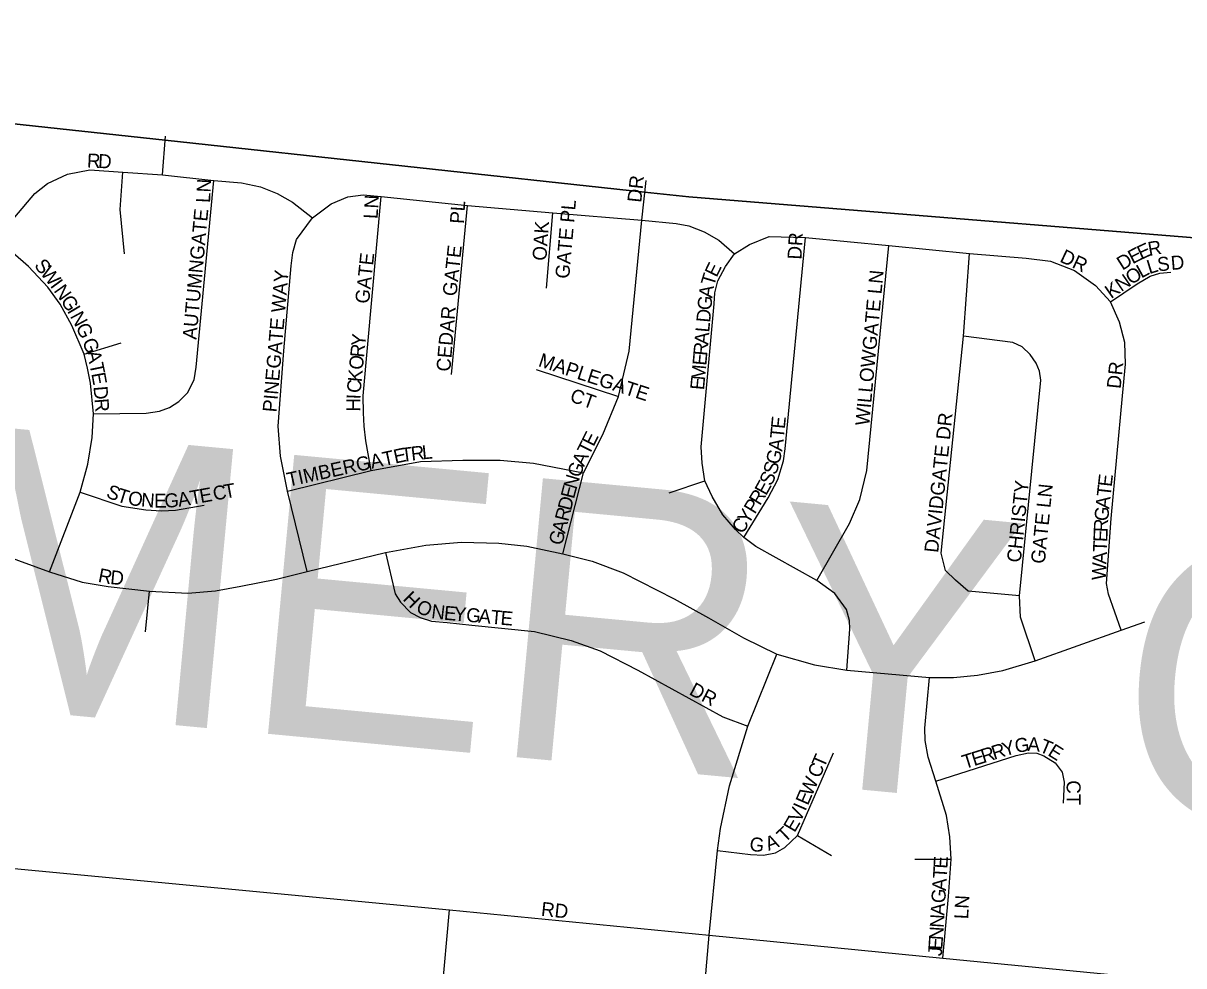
# Model space of a CAD drawing. Extents: x 0 to 680, y 0 to 440.
# Drawn here: x 73.29 to 85.58, y 268.17 to 278.15 of the extents above; entities that cross this region are included whole.
import ezdxf

# ---------------------------------------------------------------- set-up
doc = ezdxf.new("R2010")
doc.units = 0
for name, color, linetype in [('GM_X_Adjacent_County', 7, 'Continuous'), ('GM_X_Adjacent_County_Text', 7, 'Continuous'), ('GM_X_City_Street', 7, 'Continuous'), ('GM_X_City_Street_Text', 7, 'Continuous'), ('GM_X_County', 7, 'Continuous')]:
    doc.layers.add(name, color=color, linetype=linetype)

msp = doc.modelspace()

# ---------------------------------------------------------------- linework, layer by layer
at = {"layer": 'GM_X_Adjacent_County'}
for points in [[(47.02, 308.647), (47.02, 297.605), (47.136, 296.47), (47.708, 293.469), (47.673, 290.467), (48.191, 288.97), (48.899, 287.478), (50.382, 285.963), (52.043, 282.914), (53.205, 281.417), (53.473, 278.963), (55.844, 278.74), (63.104, 278.067), (70.999, 277.32), (74.792, 276.91), (79.867, 276.361), (80.338, 276.31), (87.389, 275.738), (92.667, 275.254), (94.764, 275.075), (102.624, 274.346)], [(47.02, 308.647), (47.02, 297.605), (47.136, 296.47), (47.708, 293.469), (47.673, 290.467), (48.191, 288.97), (48.899, 287.478), (50.382, 285.963), (52.043, 282.914), (53.205, 281.417), (53.473, 278.963), (55.844, 278.74), (63.104, 278.067), (70.999, 277.32), (74.792, 276.91), (79.867, 276.361), (80.338, 276.31), (87.389, 275.738), (92.667, 275.254), (94.764, 275.075), (102.624, 274.346)], [(102.624, 274.346), (94.764, 275.075), (92.667, 275.254), (87.389, 275.738), (80.338, 276.31), (79.867, 276.361), (74.792, 276.91), (70.999, 277.32), (63.104, 278.067), (55.844, 278.74), (53.473, 278.963), (53.205, 281.417), (52.043, 282.914), (50.382, 285.963), (48.899, 287.478), (48.191, 288.97), (47.673, 290.467), (47.708, 293.469), (47.136, 296.47), (47.02, 297.605), (47.02, 177.346)]]:
    msp.add_lwpolyline(points, dxfattribs=at)
at = {"layer": 'GM_X_City_Street'}
for points in [[(74.765, 276.544), (74.796, 276.954)], [(70.942, 275.595), (71.129, 275.57), (71.625, 275.511), (71.91, 275.482), (72.13, 275.465), (72.374, 275.465), (72.629, 275.523), (72.833, 275.65), (73.039, 275.839), (73.202, 276.096), (73.411, 276.346), (73.546, 276.451), (73.759, 276.551), (73.994, 276.598), (74.345, 276.573), (74.765, 276.544), (75.307, 276.485), (75.602, 276.457), (75.803, 276.417), (75.979, 276.347), (76.14, 276.253), (76.351, 276.087)], [(74.033, 274.016), (74.591, 274.022), (74.732, 274.041), (74.838, 274.081), (74.938, 274.146), (75.029, 274.236), (75.098, 274.373), (75.121, 274.509), (75.177, 275.104), (75.307, 276.485)], [(74.363, 275.706), (74.317, 276.175), (74.345, 276.573)], [(79.004, 272.534), (79.22, 273.39), (79.425, 273.797), (79.591, 274.197), (79.703, 274.677), (79.839, 276.063), (79.883, 276.484)], [(76.295, 272.347), (76.086, 273.197), (76.015, 273.565), (75.988, 273.884), (76.047, 274.682), (76.126, 275.58), (76.143, 275.722), (76.182, 275.859), (76.351, 276.087), (76.55, 276.237), (76.725, 276.31), (76.887, 276.332), (77.079, 276.314), (77.994, 276.22), (78.895, 276.14), (79.839, 276.063), (80.201, 276.028), (80.337, 276.004), (80.5, 275.94), (80.655, 275.852), (80.82, 275.706)], [(76.973, 273.414), (76.917, 273.729), (76.898, 273.884), (76.892, 274.026), (76.887, 274.204), (77.079, 276.314)], [(77.823, 274.431), (77.994, 276.22)], [(78.828, 275.343), (78.895, 276.14)], [(82.009, 271.302), (82.041, 271.736), (82.036, 271.829), (82.005, 271.944), (81.881, 272.113), (81.691, 272.25), (81.044, 272.611), (80.918, 272.706), (80.832, 272.789), (80.697, 272.947), (80.582, 273.141), (80.506, 273.305), (80.476, 273.492), (80.467, 273.666), (80.603, 275.178), (80.612, 275.295), (80.645, 275.422), (80.724, 275.573), (80.82, 275.706), (80.977, 275.805), (81.185, 275.89), (81.57, 275.881), (82.455, 275.794), (83.309, 275.712), (83.909, 275.663), (84.164, 275.629), (84.419, 275.53), (84.643, 275.372), (84.801, 275.201)], [(80.918, 272.706), (81.177, 273.124), (81.277, 273.32), (81.34, 273.518), (81.355, 273.644), (81.57, 275.881)], [(73.567, 272.341), (73.894, 273.186), (73.972, 273.481), (74.021, 273.763), (74.033, 274.016), (74.001, 274.339), (73.969, 274.496), (73.935, 274.646), (73.805, 274.948), (73.682, 275.174), (73.55, 275.353), (73.346, 275.573), (73.039, 275.839)], [(81.691, 272.25), (82.038, 272.853), (82.147, 273.108), (82.221, 273.414), (82.455, 275.794)], [(83.836, 272.09), (83.293, 272.138), (83.16, 272.253), (83.054, 272.358), (83.007, 272.539), (83.244, 274.838), (83.309, 275.712)], [(84.801, 275.201), (85.084, 275.391), (85.222, 275.47), (85.322, 275.504), (85.439, 275.512)], [(84.914, 271.727), (84.78, 272.106), (84.758, 272.22), (84.806, 272.907), (84.926, 274.206), (84.958, 274.54), (84.953, 274.771), (84.897, 274.983), (84.801, 275.201)], [(73.935, 274.646), (74.325, 274.766)], [(84.002, 271.402), (83.847, 271.862), (83.836, 272.09), (84.064, 274.372), (84.049, 274.465), (84.014, 274.551), (83.95, 274.644), (83.866, 274.722), (83.765, 274.771), (83.244, 274.838)], [(78.719, 274.485), (79.591, 274.197)], [(76.086, 273.197), (76.973, 273.414), (77.496, 273.509), (77.942, 273.523), (78.338, 273.523), (78.693, 273.491), (79.22, 273.39)], [(80.129, 273.179), (80.506, 273.305)], [(73.894, 273.186), (74.335, 273.037), (74.587, 272.997), (74.752, 272.988), (74.901, 272.995), (75.206, 273.048)], [(72.764, 272.634), (73.567, 272.341), (73.915, 272.232), (74.19, 272.189), (74.625, 272.137), (75.031, 272.118), (75.325, 272.141), (75.593, 272.19), (75.972, 272.264), (76.295, 272.347), (77.126, 272.547), (77.553, 272.626), (77.93, 272.655), (78.325, 272.645), (78.622, 272.615), (79.004, 272.534)], [(77.126, 272.547), (77.227, 272.111), (77.283, 272.021), (77.39, 271.912), (77.491, 271.858), (77.612, 271.822), (77.778, 271.806), (78.038, 271.777), (78.702, 271.711), (79.09, 271.617), (79.396, 271.508), (79.798, 271.302), (80.697, 270.81), (80.961, 270.708)], [(79.004, 272.534), (79.313, 272.457), (79.641, 272.333), (80.181, 272.058), (80.543, 271.856), (80.914, 271.645), (81.268, 271.471), (81.665, 271.36), (82.009, 271.302), (82.883, 271.224), (83.14, 271.225), (83.394, 271.248), (83.66, 271.298), (84.002, 271.402), (84.914, 271.727), (85.164, 271.814)], [(74.585, 271.708), (74.625, 272.137)], [(80.473, 267.6), (80.552, 268.499), (80.641, 269.394), (80.67, 269.626), (80.766, 270.078), (80.961, 270.708), (81.268, 271.471)], [(83.026, 268.256), (83.085, 268.907), (83.113, 269.304), (83.1, 269.54), (83.063, 269.763), (82.951, 270.127), (82.871, 270.38), (82.839, 270.557), (82.836, 270.689), (82.883, 271.224)], [(80.641, 269.394), (80.99, 269.353), (81.125, 269.346), (81.253, 269.371), (81.352, 269.427), (81.486, 269.554), (81.869, 270.426)], [(82.951, 270.127), (83.803, 270.399), (83.932, 270.426), (84.02, 270.424), (84.095, 270.396), (84.214, 270.323), (84.287, 270.223), (84.31, 270.116), (84.299, 269.895)], [(70.367, 269.473), (77.802, 268.765), (80.552, 268.499), (83.026, 268.256), (86.292, 267.936), (89.501, 267.603), (91.209, 267.449), (91.849, 267.397), (92.491, 267.422), (93.212, 267.516), (93.58, 267.534), (93.89, 267.521), (96.364, 267.28), (101.905, 266.772)], [(81.486, 269.554), (81.845, 269.342)], [(82.729, 269.304), (83.113, 269.304)], [(75.007, 265.475), (75.441, 265.433), (75.655, 265.41), (75.889, 265.413), (76.086, 265.452), (76.339, 265.55), (76.556, 265.69), (77.106, 266.138), (77.461, 266.474), (77.54, 266.646), (77.613, 266.834), (77.646, 267.011), (77.721, 267.865), (77.802, 268.765)]]:
    msp.add_lwpolyline(points, dxfattribs=at)
at = {"layer": 'GM_X_County'}
msp.add_lwpolyline([(102.624, 274.346), (94.764, 275.075), (92.667, 275.254), (87.389, 275.738), (80.338, 276.31), (79.867, 276.361), (74.792, 276.91), (70.999, 277.32), (63.104, 278.067), (55.844, 278.74), (53.473, 278.963), (53.205, 281.417), (52.043, 282.914), (50.382, 285.963), (48.899, 287.478), (48.191, 288.97), (47.673, 290.467), (47.708, 293.469), (47.136, 296.47), (47.02, 297.605), (47.02, 177.346)], dxfattribs=at)

# ---------------------------------------------------------------- texts
at = {"layer": 'GM_X_Adjacent_County_Text'}
msp.add_text('MONTGOMERY COUNTY', height=2.96462, rotation=354.6312, dxfattribs=at).set_placement((54.51, 272.637))
at = {"layer": 'GM_X_City_Street_Text'}
for s, height, rotation, p in [('R', 0.148, 357.4007, (73.962, 276.622)), ('D', 0.148, 356.6759, (74.079, 276.617)), ('LN', 0.1482, 86.989, (75.267, 276.244)), ('DR', 0.1482, 83.9946, (79.832, 276.245)), ('LN', 0.1482, 86.8222, (77.041, 276.074)), ('PL', 0.1482, 86.1879, (77.954, 276.022)), ('GATE PL', 0.1482, 84.9861, (79.069, 275.44)), ('AUTUMNGATE', 0.1482, 84.7521, (75.123, 274.796)), ('OAK', 0.1482, 86.1811, (78.828, 275.631)), ('DR', 0.1482, 86.8222, (81.528, 275.644)), ('R', 0.148, 10.0572, (85.21, 275.684)), ('GATE', 0.1482, 83.9264, (77.876, 275.254)), ('DR', 0.1482, 334.7921, (84.254, 275.628)), ('E', 0.148, 27.457, (85.034, 275.596)), ('E', 0.148, 24.8419, (85.125, 275.643)), ('S', 0.148, 309.0395, (73.399, 275.581)), ('GATE', 0.1482, 83.931, (76.95, 275.175)), ('E', 0.148, 64.1314, (80.63, 275.451)), ('D', 0.148, 32.4108, (84.927, 275.528)), ('L', 0.148, 17.0786, (85.211, 275.492)), ('S', 0.148, 6.0505, (85.303, 275.521)), ('D', 0.148, 4.9234, (85.445, 275.536)), ('W', 0.148, 308.6152, (73.464, 275.501)), ('PINEGATE WAY', 0.14823, 85.1021, (75.971, 274.027)), ('T', 0.148, 73.0861, (80.602, 275.357)), ('WILLOWGATE LN', 0.14823, 84.6282, (82.245, 273.884)), ('N', 0.148, 34.6357, (84.914, 275.301)), ('O', 0.148, 33.187, (85.02, 275.375)), ('L', 0.148, 28.8874, (85.127, 275.445)), ('I', 0.148, 306.188, (73.569, 275.369)), ('N', 0.148, 305.1693, (73.607, 275.317)), ('A', 0.148, 82.0862, (80.585, 275.234)), ('K', 0.148, 34.8237, (84.807, 275.227)), ('G', 0.148, 302.0957, (73.681, 275.212)), ('G', 0.148, 84.8679, (80.573, 275.106)), ('I', 0.148, 300.6939, (73.75, 275.103)), ('CEDAR', 0.1482, 85.1336, (77.81, 274.457)), ('D', 0.148, 84.857, (80.562, 274.976)), ('N', 0.148, 298.286, (73.782, 275.048)), ('G', 0.148, 294.0135, (73.843, 274.936)), ('Y', 0.148, 84.396, (76.908, 274.723)), ('A', 0.148, 84.857, (80.541, 274.742)), ('L', 0.148, 84.8604, (80.552, 274.872)), ('G', 0.148, 291.8582, (73.911, 274.782)), ('R', 0.148, 84.4104, (76.897, 274.606)), ('R', 0.148, 84.8693, (80.53, 274.625)), ('A', 0.148, 284.084, (73.958, 274.666)), ('O', 0.148, 84.396, (76.884, 274.476)), ('MAPLEGATE', 0.1482, 341.9956, (78.734, 274.521)), ('E', 0.148, 84.8604, (80.521, 274.521)), ('T', 0.148, 281.6636, (73.989, 274.541)), ('M', 0.148, 84.8553, (80.507, 274.365)), ('DR', 0.1482, 83.9946, (84.907, 274.275)), ('E', 0.148, 280.3024, (74.01, 274.44)), ('C', 0.148, 85.0891, (76.862, 274.23)), ('K', 0.148, 84.4177, (76.872, 274.346)), ('E', 0.148, 84.8575, (80.497, 274.262)), ('D', 0.148, 274.9234, (74.033, 274.302)), ('CT', 0.1482, 340.5566, (79.067, 274.149)), ('R', 0.148, 274.449, (74.044, 274.172)), ('H', 0.148, 89.6721, (76.858, 274.037)), ('I', 0.148, 87.463, (76.859, 274.166)), ('DAVIDGATE DR', 0.14823, 84.0745, (82.976, 272.54)), ('T', 0.148, 84.3007, (81.342, 273.747)), ('E', 0.148, 84.4529, (81.352, 273.851)), ('E', 0.148, 63.4349, (79.327, 273.661)), ('TIMBERGATE', 0.1482, 12.1816, (76.097, 273.243)), ('T', 0.148, 7.5351, (77.3, 273.504)), ('R', 0.148, 6.89, (77.403, 273.518)), ('L', 0.148, 5.5284, (77.518, 273.532)), ('T', 0.148, 63.4349, (79.28, 273.567)), ('A', 0.148, 82.621, (81.324, 273.613)), ('A', 0.148, 65.4509, (79.227, 273.45)), ('S', 0.148, 74.2915, (81.262, 273.362)), ('G', 0.148, 77.2379, (81.293, 273.471)), ('G', 0.148, 69.4828, (79.182, 273.33)), ('S', 0.148, 64.8058, (81.209, 273.243)), ('T', 0.148, 10.19, (75.427, 273.117)), ('N', 0.148, 73.5148, (79.146, 273.208)), ('E', 0.148, 61.2934, (81.154, 273.142)), ('CHRISTY', 0.1482, 84.193, (83.85, 272.436)), ('GATE LN', 0.1482, 84.193, (84.104, 272.423)), ('T', 0.148, 83.6477, (84.801, 273.134)), ('E', 0.148, 83.6625, (84.813, 273.238)), ('S', 0.148, 337.1637, (74.158, 273.137)), ('T', 0.148, 342.7548, (74.269, 273.091)), ('O', 0.148, 350.888, (74.391, 273.055)), ('N', 0.148, 355.4881, (74.533, 273.033)), ('E', 0.148, 0.1204, (74.676, 273.022)), ('G', 0.148, 2.484, (74.787, 273.022)), ('A', 0.148, 9.5001, (74.937, 273.03)), ('T', 0.148, 10.1963, (75.067, 273.052)), ('E', 0.148, 10.21, (75.17, 273.07)), ('C', 0.148, 10.2049, (75.311, 273.096)), ('D', 0.148, 75.5308, (79.088, 272.982)), ('E', 0.148, 75.5308, (79.12, 273.108)), ('R', 0.148, 58.684, (81.089, 273.036)), ('R', 0.148, 75.5308, (79.058, 272.868)), ('Y', 0.148, 58.6202, (80.967, 272.835)), ('P', 0.148, 58.6287, (81.035, 272.946)), ('G', 0.148, 84.9006, (84.776, 272.875)), ('A', 0.148, 83.6936, (84.787, 273.004)), ('C', 0.148, 58.628, (80.906, 272.735)), ('R', 0.148, 87.4007, (84.77, 272.76)), ('G', 0.148, 75.5308, (78.993, 272.615)), ('A', 0.148, 75.5308, (79.026, 272.742)), ('E', 0.148, 87.6927, (84.766, 272.656)), ('T', 0.148, 87.6766, (84.762, 272.551)), ('A', 0.148, 87.6823, (84.757, 272.421)), ('W', 0.148, 87.6791, (84.75, 272.252)), ('R', 0.148, 348.9044, (74.075, 272.238)), ('D', 0.148, 354.3582, (74.206, 272.214)), ('H', 0.148, 314.8764, (77.3, 272.048)), ('O', 0.148, 334.6292, (77.437, 271.924)), ('N', 0.148, 353.1184, (77.605, 271.854)), ('E', 0.148, 354.7719, (77.739, 271.837)), ('Y', 0.148, 354.9472, (77.844, 271.828)), ('G', 0.148, 354.9697, (77.974, 271.816)), ('A', 0.148, 354.9697, (78.104, 271.805)), ('T', 0.148, 354.9735, (78.234, 271.794)), ('E', 0.148, 354.9391, (78.338, 271.784)), ('DR', 0.1482, 332.1033, (80.33, 271.049)), ('Y', 0.148, 16.783, (83.679, 270.388)), ('G', 0.148, 9.5737, (83.799, 270.425)), ('A', 0.148, 357.7041, (83.919, 270.446)), ('T', 0.148, 337.5188, (84.036, 270.444)), ('E', 0.148, 17.4804, (83.356, 270.286)), ('R', 0.148, 17.4598, (83.455, 270.318)), ('R', 0.148, 17.4463, (83.567, 270.353)), ('E', 0.148, 327.7949, (84.127, 270.407)), ('C', 0.148, 66.4943, (81.721, 270.151)), ('T', 0.148, 66.52, (81.768, 270.259)), ('T', 0.148, 17.4502, (83.256, 270.255)), ('W', 0.148, 66.4967, (81.638, 269.96)), ('CT', 0.1482, 270, (84.336, 270.137)), ('E', 0.148, 66.503, (81.596, 269.864)), ('V', 0.148, 66.1932, (81.517, 269.684)), ('I', 0.148, 66.484, (81.57, 269.804)), ('E', 0.148, 59.672, (81.456, 269.577)), ('T', 0.148, 43.9277, (81.354, 269.47)), ('G', 0.148, 353.626, (80.973, 269.392)), ('A', 0.148, 21.5792, (81.18, 269.388)), ('T', 0.148, 86.3933, (83.067, 269.094)), ('E', 0.148, 86.7224, (83.073, 269.199)), ('A', 0.148, 86.3898, (83.058, 268.964)), ('G', 0.148, 86.3898, (83.05, 268.833)), ('RD', 0.1482, 353.9832, (78.767, 268.704)), ('LN', 0.1482, 86.9884, (83.293, 268.665)), ('A', 0.148, 86.3898, (83.042, 268.703)), ('N', 0.148, 86.3898, (83.034, 268.573)), ('N', 0.148, 86.3898, (83.026, 268.443)), ('J', 0.148, 86.4128, (83.015, 268.274)), ('E', 0.148, 86.3913, (83.019, 268.339))]:
    msp.add_text(s, height=height, rotation=rotation, dxfattribs=at).set_placement(p)

doc.saveas('drawing.dxf')
